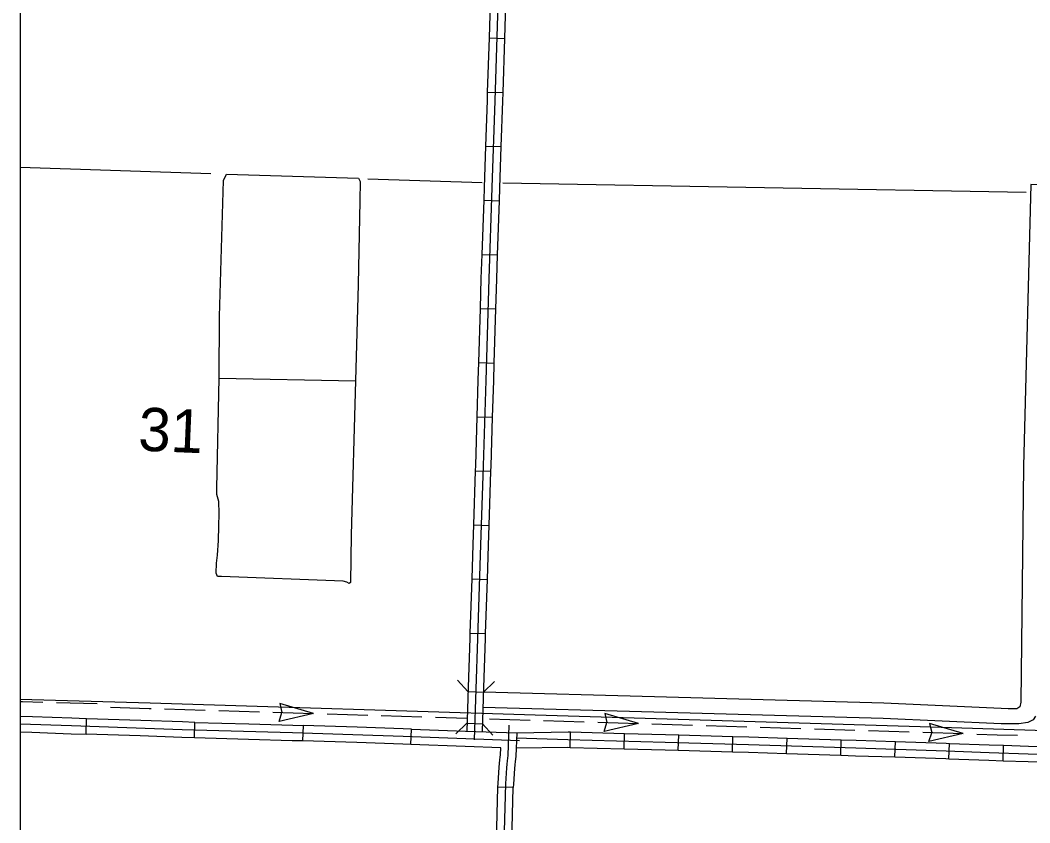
# Model space of a CAD drawing. Extents: x 1196286 to 1268366, y 2040822 to 2082115.
# Drawn here: x 1214333 to 1218023, y 2053681 to 2056617 of the extents above; entities that cross this region are included whole.
import ezdxf

# ---------------------------------------------------------------- set-up
doc = ezdxf.new("R2010")
doc.units = 0
for name, color, linetype in [('60', 7, 'Continuous'), ('61', 7, 'Continuous'), ('62', 7, 'Continuous'), ('63', 7, 'Continuous'), ('Level 71', 7, 'Continuous'), ('Level 72', 7, 'Continuous'), ('Level 8', 7, 'Continuous'), ('Level 83', 7, 'Continuous')]:
    doc.layers.add(name, color=color, linetype=linetype)

msp = doc.modelspace()

# ---------------------------------------------------------------- linework, layer by layer
at = {"layer": '60'}
for points in [[(1214332.8, 2056079), (1215029.1, 2056056.2)], [(1215604, 2056037.4), (1216020.9, 2056023.7)], [(1216097.1, 2056021.7), (1218009.2, 2055987.8)]]:
    msp.add_lwpolyline(points, dxfattribs=at)
at = {"layer": '61'}
for p, q in [((1216046.5, 2056552.2), (1216102.7, 2056550.5)), ((1216040.2, 2056354.4), (1216096.4, 2056352.6)), ((1216033.6, 2056156.5), (1216089.8, 2056154.6)), ((1216026.9, 2055958.6), (1216083.1, 2055956.7)), ((1216020.1, 2055760.7), (1216076.4, 2055758.8)), ((1216013.9, 2055562.7), (1216070.1, 2055561.1)), ((1216008, 2055364.8), (1216064.2, 2055363.1)), ((1216002, 2055166.9), (1216058.2, 2055165.2)), ((1215996, 2054969), (1216052.2, 2054967.3)), ((1215989.8, 2054771.1), (1216046, 2054769.4)), ((1215983.3, 2054573.3), (1216039.5, 2054571.4)), ((1215976.5, 2054375.4), (1216032.7, 2054373.5)), ((1215969.5, 2054161.5), (1216025.8, 2054159.7)), ((1215965.8, 2054045.2), (1216022, 2054043.4)), ((1216342.5, 2053957.3), (1216344, 2054013.6)), ((1216540.4, 2053952), (1216541.9, 2054008.2)), ((1216738.3, 2053946.6), (1216739.9, 2054002.9)), ((1216936.2, 2053941.2), (1216937.8, 2053997.4)), ((1217134, 2053935), (1217135.8, 2053991.3)), ((1217331.9, 2053928.6), (1217333.7, 2053984.8)), ((1217529.8, 2053922.2), (1217531.6, 2053978.4)), ((1217727.5, 2053915.7), (1217729.7, 2053971.9)), ((1217925.7, 2053908.4), (1217927.2, 2053964.7))]:
    msp.add_line(p, q, dxfattribs=at)
for points in [[(1216129.5, 2057936), (1216123.1, 2057796.1), (1216118.2, 2057658.9), (1216108, 2057351.5), (1216097.7, 2057044.6), (1216096, 2057008), (1216095.2, 2057002.4), (1216094.2, 2056996.1), (1216092.4, 2056989), (1216091.1, 2056979.8), (1216090.8, 2056970.6), (1216090.6, 2056958.8), (1216090.2, 2056949), (1216089.7, 2056937.8), (1216077.3, 2056635.7), (1216067.3, 2056322.4), (1216056.6, 2056004.9), (1216045.2, 2055671.3), (1216034.2, 2055299.4), (1216024.7, 2054987.1), (1216015.7, 2054698.1), (1216004, 2054355.8), (1215992, 2053985.2)], [(1216053.9, 2056750.4), (1216049.2, 2056636.7), (1216046.5, 2056552.2)], [(1216110.1, 2056748.1), (1216105.4, 2056634.6), (1216102.7, 2056550.5)], [(1216046.5, 2056552.2), (1216040.2, 2056354.4)], [(1216102.7, 2056550.5), (1216096.4, 2056352.6)], [(1216040.2, 2056354.4), (1216039.2, 2056323.4), (1216033.6, 2056156.5)], [(1216096.4, 2056352.6), (1216095.4, 2056321.5), (1216089.8, 2056154.6)], [(1216033.6, 2056156.5), (1216028.5, 2056005.8), (1216026.9, 2055958.6)], [(1216089.8, 2056154.6), (1216084.7, 2056003.9), (1216083.1, 2055956.7)], [(1216026.9, 2055958.6), (1216020.1, 2055760.7)], [(1216083.1, 2055956.7), (1216076.4, 2055758.8)], [(1216020.1, 2055760.7), (1216017.1, 2055672.2), (1216013.9, 2055562.7)], [(1216076.4, 2055758.8), (1216073.4, 2055670.4), (1216070.1, 2055561.1)], [(1216013.9, 2055562.7), (1216008, 2055364.8)], [(1216070.1, 2055561.1), (1216064.2, 2055363.1)], [(1216008, 2055364.8), (1216006.1, 2055300.2), (1216002, 2055166.9)], [(1216064.2, 2055363.1), (1216062.3, 2055298.5), (1216058.2, 2055165.2)], [(1216002, 2055166.9), (1215996.6, 2054988), (1215996, 2054969)], [(1216058.2, 2055165.2), (1216052.8, 2054986.3), (1216052.2, 2054967.3)], [(1215996, 2054969), (1215989.8, 2054771.1)], [(1216052.2, 2054967.3), (1216046, 2054769.4)], [(1215989.8, 2054771.1), (1215987.6, 2054699), (1215983.3, 2054573.3)], [(1216046, 2054769.4), (1216043.8, 2054697.2), (1216039.5, 2054571.4)], [(1215983.3, 2054573.3), (1215976.5, 2054375.4)], [(1216039.5, 2054571.4), (1216032.7, 2054373.5)], [(1215976.5, 2054375.4), (1215975.8, 2054356.8), (1215970.1, 2054177.5)], [(1216032.7, 2054373.5), (1216032.1, 2054354.9), (1216026.3, 2054175.7)], [(1215970.1, 2054177.5), (1215964.9, 2054016.8)], [(1216026.3, 2054175.7), (1216021.1, 2054014.7)], [(1216147.6, 2054010), (1216335.6, 2054013.8), (1216344, 2054013.6)], [(1216344, 2054013.6), (1216541.9, 2054008.2)], [(1216541.9, 2054008.2), (1216691.2, 2054004.2), (1216739.9, 2054002.9)], [(1216145.3, 2053991.9), (1216334.7, 2053985.7), (1216690.4, 2053976.1), (1216995.2, 2053967.7), (1217387.2, 2053954.9), (1217716.9, 2053944.3), (1217874.2, 2053938), (1218017.6, 2053934), (1218331, 2053923.6), (1218663, 2053912), (1218845.9, 2053906.4), (1218988.8, 2053901.5), (1219319.5, 2053893.5), (1219691.4, 2053884.9), (1220058.9, 2053875.7), (1220356.5, 2053867.7), (1220363.8, 2053867.4), (1220367.8, 2053867.3), (1220369.5, 2053867.2), (1220388.4, 2053850.9)], [(1216739.9, 2054002.9), (1216937.8, 2053997.4)], [(1216937.8, 2053997.4), (1216996.1, 2053995.8), (1217135.8, 2053991.3)], [(1217135.8, 2053991.3), (1217333.7, 2053984.8)], [(1217333.7, 2053984.8), (1217388.1, 2053983.1), (1217531.6, 2053978.4)], [(1217531.6, 2053978.4), (1217717.9, 2053972.4), (1217729.7, 2053971.9)], [(1217729.7, 2053971.9), (1217875.1, 2053966.1), (1217927.2, 2053964.7)], [(1216145.8, 2053955.3), (1216333.9, 2053957.6), (1216342.5, 2053957.3)], [(1216342.5, 2053957.3), (1216540.4, 2053952)], [(1216540.4, 2053952), (1216689.7, 2053948), (1216738.3, 2053946.6)], [(1216738.3, 2053946.6), (1216936.2, 2053941.2)], [(1216936.2, 2053941.2), (1216994.4, 2053939.6), (1217134, 2053935)], [(1217134, 2053935), (1217331.9, 2053928.6)], [(1217927.2, 2053964.7), (1218018.4, 2053962.1), (1218125.3, 2053958.6)], [(1217331.9, 2053928.6), (1217386.3, 2053926.8), (1217529.8, 2053922.2)], [(1217529.8, 2053922.2), (1217715.9, 2053916.2), (1217727.5, 2053915.7)], [(1217727.5, 2053915.7), (1217873.2, 2053909.9), (1217925.7, 2053908.4)], [(1217925.7, 2053908.4), (1218016.7, 2053905.9), (1218123.4, 2053902.4)]]:
    msp.add_lwpolyline(points, dxfattribs=at)
at = {"layer": '62'}
for points in [[(1215061, 2055533.2), (1215075.7, 2056031.3), (1215087.1, 2056053.4), (1215569.9, 2056039.4), (1215576, 2056026.8), (1215573.9, 2055956.1), (1215568.3, 2055650.3)], [(1215568.3, 2055650.3), (1215558.3, 2055298.1)], [(1215060.2, 2055307.3), (1215061, 2055533.2)], [(1215058.4, 2054766.3), (1215060.4, 2054812.5), (1215058.5, 2054856.9), (1215051, 2054881.8), (1215051.1, 2054905.4), (1215060.2, 2055307.3)], [(1215060.2, 2055307.3), (1215558.3, 2055298.1)], [(1215558.3, 2055298.1), (1215542.4, 2054735.2)], [(1215542.4, 2054735.2), (1215539.6, 2054560.6), (1215535.6, 2054556.1), (1215526.4, 2054562.1), (1215513.3, 2054564.6), (1215068.4, 2054581.7), (1215054.3, 2054582.3), (1215049.1, 2054594.8), (1215050.7, 2054631.6), (1215053.8, 2054659.8), (1215058, 2054713.5), (1215058.4, 2054766.3)]]:
    msp.add_lwpolyline(points, dxfattribs=at)
at = {"layer": '63'}
for p, q in [((1215405, 2054081.1), (1215281.8, 2054118.2)), ((1215281.8, 2054118.2), (1215289.6, 2054084.9)), ((1215279.7, 2054051.7), (1215289.6, 2054084.5)), ((1215405, 2054081.1), (1215279.7, 2054051.7)), ((1216592.5, 2054044.3), (1216469.2, 2054081.5)), ((1216469.2, 2054081.5), (1216477.1, 2054048.2)), ((1216467.2, 2054014.9), (1216477.1, 2054047.7)), ((1216592.5, 2054044.3), (1216467.2, 2054014.9)), ((1217779.9, 2054007.5), (1217656.7, 2054044.7)), ((1217656.7, 2054044.7), (1217664.5, 2054011.4)), ((1217654.6, 2053978.1), (1217664.5, 2054010.9)), ((1217779.9, 2054007.5), (1217654.6, 2053978.1))]:
    msp.add_line(p, q, dxfattribs=at)
for points in [[(1214332.8, 2054133.5), (1214807.4, 2054120.1), (1216214.7, 2054076.6), (1217621.9, 2054033), (1218997.4, 2053989.8), (1221006.7, 2053936.6), (1222316.5, 2053925.4), (1224541.8, 2053870.1), (1226049.9, 2053825), (1226066.5, 2053822.1), (1226073, 2053820), (1226078.6, 2053817.2), (1226086.5, 2053812.4), (1226093.5, 2053807.1), (1226100.5, 2053799.7), (1226108, 2053791.1)], [(1214332.8, 2054133.5), (1214807.4, 2054120.1), (1216214.7, 2054076.6), (1217621.9, 2054033), (1218997.4, 2053989.8), (1221006.7, 2053936.6), (1222316.5, 2053925.4), (1224541.8, 2053870.1), (1226049.9, 2053825), (1226066.5, 2053822.1), (1226073, 2053820), (1226078.6, 2053817.2), (1226086.5, 2053812.4), (1226093.5, 2053807.1), (1226100.5, 2053799.7), (1226108, 2053791.1)], [(1214332.8, 2054125.3), (1214341.8, 2054125)], [(1214341.8, 2054125), (1214416, 2054123)], [(1214465.5, 2054121.6), (1214613.9, 2054117.4)], [(1214662.9, 2054103.7), (1214804.5, 2054099.7), (1214811.3, 2054099.5)], [(1214860.8, 2054097.9), (1215009.2, 2054093.4)], [(1215058.7, 2054091.8), (1215207.1, 2054087.2)], [(1215256.6, 2054085.7), (1215405, 2054081.1)], [(1215454.5, 2054079.6), (1215528.7, 2054077.3)], [(1215528.7, 2054077.3), (1215602.9, 2054075)], [(1215652.4, 2054073.4), (1215800.8, 2054068.9)], [(1215850.3, 2054067.3), (1215966.4, 2054063.7)], [(1216048.2, 2054061.2), (1216196.6, 2054056.6)], [(1216246.1, 2054055.1), (1216394.6, 2054050.5)], [(1216444, 2054048.9), (1216592.5, 2054044.3)], [(1216641.9, 2054042.8), (1216716.1, 2054040.5)], [(1216716.1, 2054040.5), (1216790.4, 2054038.2)], [(1216839.8, 2054036.7), (1216988.3, 2054032.1)], [(1217037.7, 2054030.6), (1217186.2, 2054026)], [(1217235.6, 2054024.4), (1217384.1, 2054019.8)], [(1217433.6, 2054018.3), (1217582, 2054013.7)], [(1217631.5, 2054012.2), (1217779.9, 2054007.5)], [(1217829.4, 2054006), (1217903.6, 2054003.6)], [(1217903.6, 2054003.6), (1217977.8, 2054001.3)]]:
    msp.add_lwpolyline(points, dxfattribs=at)
at = {"layer": 'Level 71'}
for p, q in [((1214332.8, 2054070.4), (1214332.8, 2054014.1)), ((1214377.6, 2054068.8), (1214332.8, 2054070.4)), ((1214969.4, 2053992.4), (1214971.1, 2054048.6)), ((1214332.8, 2054014.1), (1214375.5, 2054012.5)), ((1215366.9, 2054036.7), (1215365.2, 2053980.5)), ((1215760.8, 2053968), (1215762.9, 2054024.2)), ((1215365.2, 2053980.5), (1215365.2, 2053980.5)), ((1216135.2, 2053810.5), (1216078.9, 2053812.1))]:
    msp.add_line(p, q, dxfattribs=at)
for points in [[(1216157.6, 2053981.5), (1215732.3, 2053997.2), (1215328, 2054009.8), (1214925, 2054021.9), (1214520.6, 2054035.4), (1214332.8, 2054042.2)], [(1214575.4, 2054061.7), (1214521.6, 2054063.5), (1214377.6, 2054068.8)], [(1214573.5, 2054005.5), (1214575.4, 2054061.7), (1214575.4, 2054061.7)], [(1214773.3, 2054055.1), (1214575.4, 2054061.7)], [(1214971.1, 2054048.6), (1214925.9, 2054050), (1214773.3, 2054055.1)], [(1214971.1, 2054048.6), (1215169, 2054042.7)], [(1215169, 2054042.7), (1215328.9, 2054037.9), (1215366.9, 2054036.7)], [(1214375.5, 2054012.5), (1214519.6, 2054007.3), (1214573.5, 2054005.5)], [(1214771.4, 2053998.9), (1214573.5, 2054005.5)], [(1215564.8, 2054030.6), (1215366.9, 2054036.7)], [(1215762.9, 2054024.2), (1215733.2, 2054025.3), (1215564.8, 2054030.6)], [(1215762.9, 2054024.2), (1215960.7, 2054016.9)], [(1215960.7, 2054016.9), (1216147.6, 2054010)], [(1216041.2, 2051980.1), (1216054.8, 2052248.1), (1216065.3, 2052467.3), (1216072.6, 2052596.5), (1216080.7, 2052772.1), (1216089.6, 2053143.9), (1216096.4, 2053435.3), (1216107.4, 2053824), (1216111.7, 2053882.4), (1216112.9, 2053895.9), (1216114.2, 2053908.2), (1216115.3, 2053918), (1216116.8, 2053927.8), (1216120.4, 2054038.5)], [(1216147.6, 2054010), (1216144.8, 2053925.2), (1216143.2, 2053914.2), (1216142.1, 2053905.1), (1216140.9, 2053893.2), (1216139.7, 2053880.1), (1216135.5, 2053822.5), (1216135.2, 2053810.5)], [(1214969.4, 2053992.4), (1214924.1, 2053993.8), (1214771.4, 2053998.9)], [(1215167.3, 2053986.5), (1214969.4, 2053992.4)], [(1215365.2, 2053980.5), (1215327.1, 2053981.7), (1215167.3, 2053986.5)], [(1215563.1, 2053974.4), (1215365.2, 2053980.5)], [(1215760.8, 2053968), (1215731.3, 2053969.1), (1215563.1, 2053974.4)], [(1215958.7, 2053960.7), (1215760.8, 2053968)], [(1216089.6, 2053955.8), (1215958.7, 2053960.7)], [(1216078.9, 2053812.1), (1216079.3, 2053825.4), (1216083.6, 2053884.6), (1216084.9, 2053898.6), (1216086.2, 2053911.3), (1216087.4, 2053921.7), (1216088.7, 2053930.3), (1216089.6, 2053955.8)], [(1216073.3, 2053614.2), (1216078.9, 2053812.1)], [(1216129.5, 2053612.6), (1216135.2, 2053810.5)]]:
    msp.add_lwpolyline(points, dxfattribs=at)
at = {"layer": 'Level 72'}
for points in [[(1218082.6, 2056015.2), (1218026.4, 2056016.7), (1217999.8, 2054985.3), (1217990.4, 2054122.7)], [(1217990.4, 2054122.7), (1217986.3, 2054105.4), (1217975.7, 2054098), (1217944.2, 2054098.7), (1217918.8, 2054099), (1217489.4, 2054119.1), (1216650.9, 2054142.5), (1216025.8, 2054159.7)], [(1218043.3, 2054071.2), (1218035.8, 2054057.8), (1218016, 2054048.3), (1217983.1, 2054043.7), (1217972.6, 2054043.8), (1217966.1, 2054043.1), (1217944.2, 2054043.6), (1217918.4, 2054042.7), (1217487.3, 2054062.9), (1216649.4, 2054086.3), (1216023.9, 2054103.5)]]:
    msp.add_lwpolyline(points, dxfattribs=at)
at = {"layer": 'Level 8'}
msp.add_lwpolyline([(1241590.6, 2065596.8), (1214332.8, 2065596.8), (1214332.8, 2047966.3), (1241590.6, 2047966.3)], close=True, dxfattribs=at)
at = {"layer": 'Level 83'}
for points in [[(1215969.5, 2054161.5), (1215931.1, 2054202.6)], [(1216066.8, 2054198.2), (1216025.8, 2054159.7)], [(1215924.7, 2054006.7), (1215965.8, 2054045.2)], [(1216022, 2054043.4), (1216060.5, 2054002.3)]]:
    msp.add_lwpolyline(points, dxfattribs=at)

# ---------------------------------------------------------------- texts
at = {"layer": '60'}
msp.add_text('31', height=158.4, rotation=357.548, dxfattribs=at).set_placement((1214762.5, 2055043.1))

doc.saveas('drawing.dxf')
